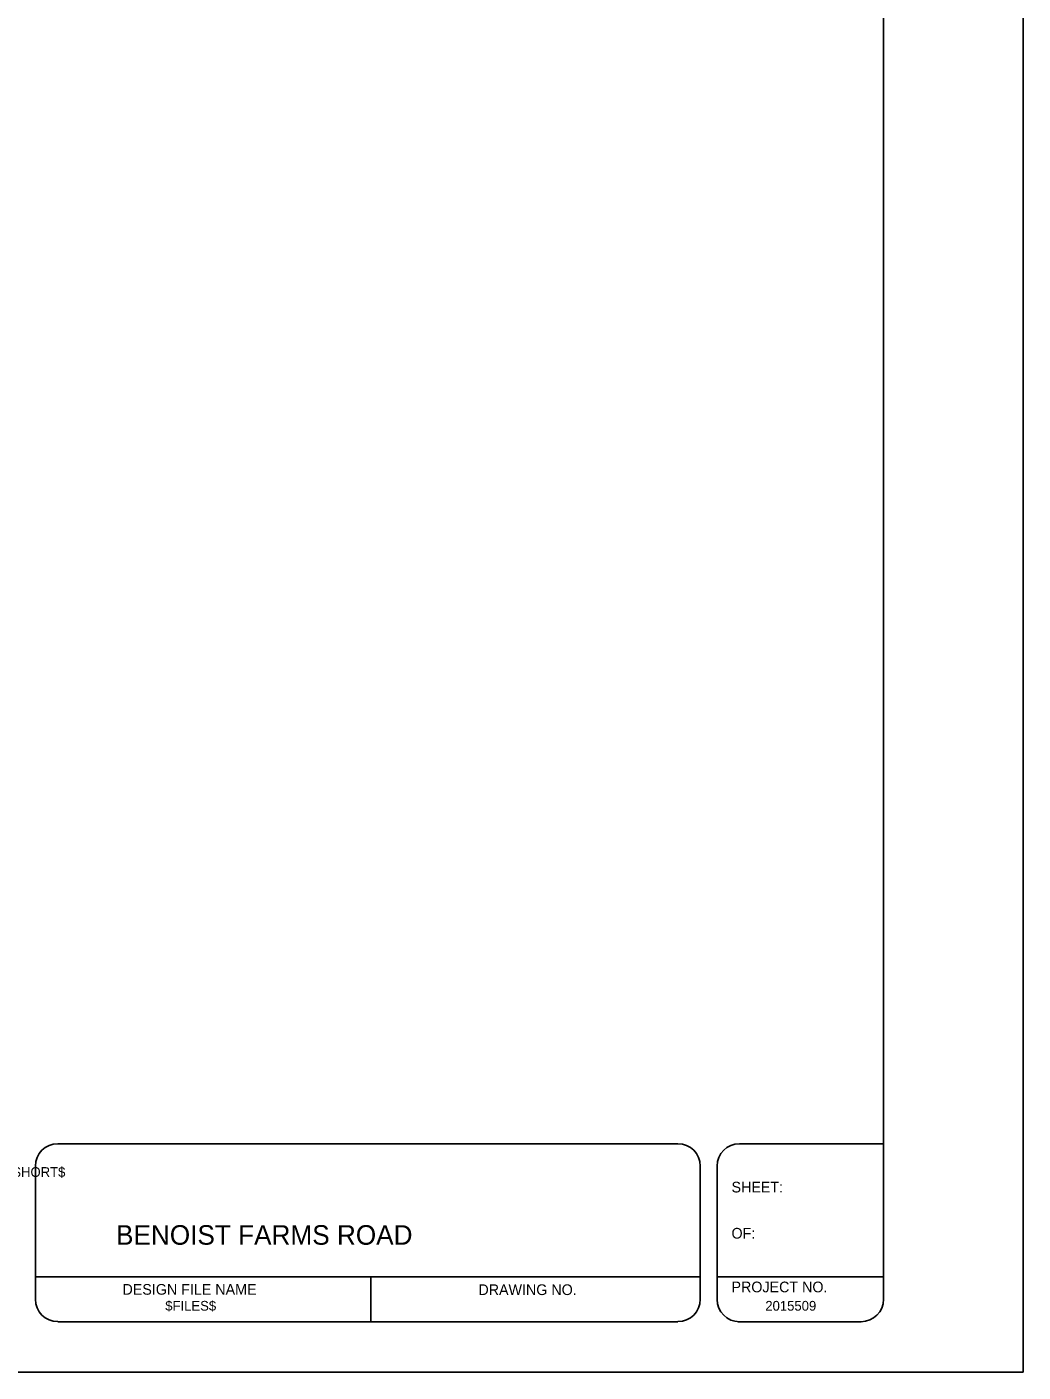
# Model space of a CAD drawing. Extents: x -0.7 to 16, y -0.9 to 9.7.
# Drawn here: x 12.02 to 15.95, y -0.9 to 4.4 of the extents above; entities that cross this region are included whole.
import ezdxf

# ---------------------------------------------------------------- set-up
doc = ezdxf.new("R2010")
doc.units = 0
for name, color, linetype in [('Default', 7, 'Continuous'), ('PlotBorder_dp', 7, 'Continuous'), ('TextLabel', 7, 'Continuous'), ('TextMisc', 7, 'Continuous')]:
    doc.layers.add(name, color=color, linetype=linetype)

msp = doc.modelspace()

# ---------------------------------------------------------------- linework, layer by layer
at = {"layer": 'Default'}
for p, q in [((15.4, -0.6133), (15.4, 9.5065)), ((14.5898, 0), (12.146, 0)), ((14.8324, 0), (15.4, 0)), ((12.0578, -0.0882), (12.0578, -0.6131)), ((14.678, -0.6135), (14.678, -0.0884)), ((14.7442, -0.6135), (14.7442, -0.0884)), ((14.6769, -0.5241), (12.0568, -0.5241)), ((13.3801, -0.7005), (13.3801, -0.5241)), ((15.4, -0.5241), (14.7475, -0.5241)), ((14.5898, -0.7014), (12.146, -0.7014)), ((15.3118, -0.7015), (14.8271, -0.7015))]:
    msp.add_line(p, q, dxfattribs=at)
for centre, major_axis, start_param, end_param in [((12.146, -0.0882), (0, 0.0882), 0, 1.570796), ((14.5898, -0.0884), (0, 0.0882), 4.712389, 6.283185), ((14.8324, -0.0884), (0, -0.0882), 3.141593, 4.712389), ((12.146, -0.6131), (0, -0.0882), 4.712389, 6.283185), ((14.5898, -0.6131), (0, 0.0882), 3.141593, 4.712389), ((14.8324, -0.6135), (0, -0.0882), 4.712389, 6.283185), ((15.3118, -0.6133), (0, -0.0882), 0, 1.570796)]:
    msp.add_ellipse(centre, major_axis=major_axis, ratio=0.999927, start_param=start_param, end_param=end_param, dxfattribs=at)
at = {"layer": 'PlotBorder_dp'}
msp.add_lwpolyline([(-0.55, -0.9), (15.95, -0.9), (15.95, 9.7), (-0.55, 9.7)], close=True, dxfattribs=at)

# ---------------------------------------------------------------- texts
at = {"layer": 'Default'}
for s, height, p in [('SHEET:', 0.04207, (14.8009, -0.1922)), ('OF:', 0.04207, (14.8009, -0.374)), ('DESIGN FILE NAME', 0.042066, (12.4009, -0.5951)), ('DRAWING NO.', 0.042066, (13.8035, -0.5964)), ('PROJECT NO.', 0.042066, (14.8009, -0.5856)), ('$FILES$', 0.03855, (12.5694, -0.6581)), ('2015509', 0.03855, (14.9341, -0.6581))]:
    msp.add_text(s, height=height, dxfattribs=at).set_placement(p)
at = {"layer": 'TextLabel'}
msp.add_text('   BENOIST FARMS ROAD   ', height=0.077091, dxfattribs=at).set_placement((12.2895, -0.3982))
at = {"layer": 'TextMisc'}
msp.add_text('$SCALESHORT$', height=0.038546, dxfattribs=at).set_placement((11.7691, -0.1311))

doc.saveas('drawing.dxf')
